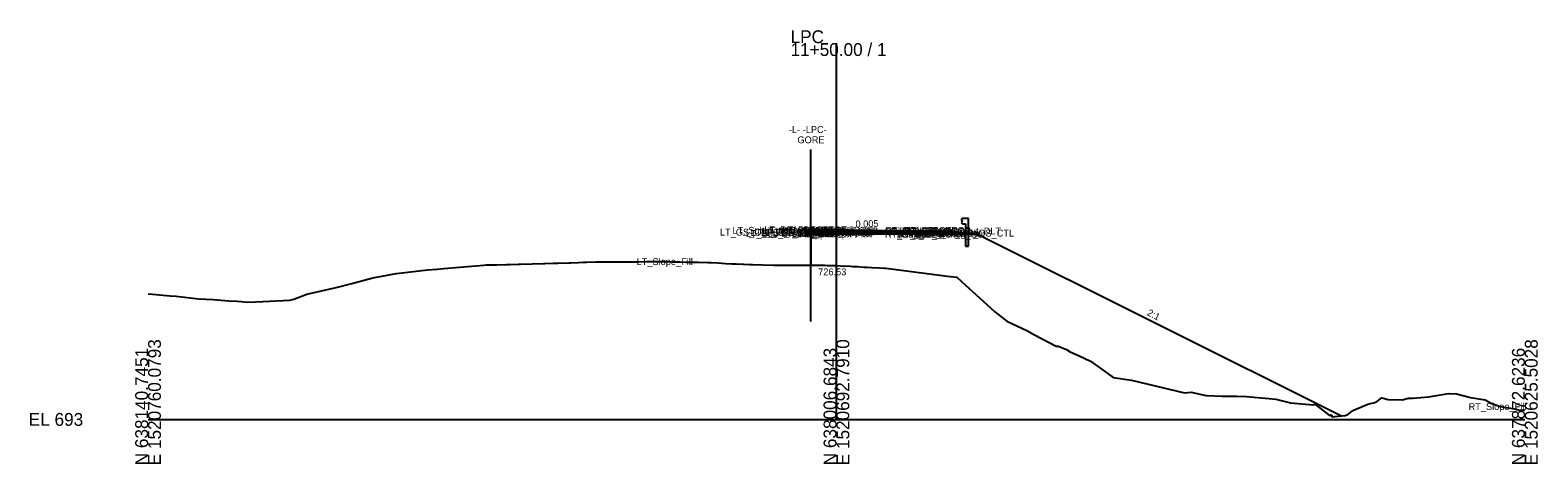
# Model space of a CAD drawing. Extents: x -26 to 303, y -10 to 4521.
# Drawn here: x -25.7 to 302.8, y 1490.3 to 1584.9 of the extents above; entities that cross this region are included whole.
import ezdxf

# ---------------------------------------------------------------- set-up
doc = ezdxf.new("R2010")
doc.units = 0
for name, color, linetype in [('Default', 7, 'Continuous'), ('Exist Cross Section Cell', 7, 'Continuous'), ('Exist XS Center Line Elevation Label', 7, 'Continuous'), ('Exist XS Ground Line', 7, 'Continuous'), ('Prop CMT Guardrail Graphics', 7, 'Continuous'), ('Prop CMT Pvmt Course 1', 7, 'Continuous'), ('Prop CMT Pvmt Course 2', 7, 'Continuous'), ('Prop CMT Pvmt Course 3', 7, 'Continuous'), ('Prop CMT Pvmt Surface', 7, 'Continuous'), ('Prop CMT Pvmt Surface Shoulder', 7, 'Continuous'), ('Prop CMT Shld Paved Course 1', 7, 'Continuous'), ('Prop CMT Shld Paved Course 2', 7, 'Continuous'), ('Prop CMT Shld Paved Course 3', 7, 'Continuous'), ('Prop CMT Slope Grass', 7, 'Continuous'), ('Prop CMT Subgrade Earthwork', 7, 'Continuous'), ('Prop XS Earthwork Shape', 7, 'Continuous'), ('Prop XS Shear Point Element', 7, 'Continuous'), ('Prop XS Shear Point Label', 7, 'Continuous')]:
    doc.layers.add(name, color=color, linetype=linetype)

msp = doc.modelspace()

# ---------------------------------------------------------------- linework, layer by layer
at = {"layer": 'Exist Cross Section Cell'}
for p, q in [((150, 1500), (150, 1582.04)), ((0, 1500), (150, 1500)), ((150, 1500), (300, 1500))]:
    msp.add_line(p, q, dxfattribs=at)
at = {"layer": 'Exist XS Ground Line'}
msp.add_lwpolyline([(0, 1527.35), (1, 1527.3), (4.04, 1527.04), (4.81, 1526.96), (6.12, 1526.87), (11.01, 1526.29), (14.21, 1526.11), (17.6, 1525.89), (19.35, 1525.77), (20.32, 1525.69), (21.74, 1525.54), (24.98, 1525.7), (30.89, 1525.98), (31.79, 1526.24), (34.61, 1527.3), (40.97, 1528.78), (44.43, 1529.67), (48.97, 1530.89), (54.08, 1531.82), (54.14, 1531.84), (60.91, 1532.64), (63.01, 1532.74), (64.44, 1532.91), (67.88, 1533.2), (73.15, 1533.64), (73.66, 1533.67), (74.34, 1533.69), (75.29, 1533.72), (75.33, 1533.71), (76, 1533.74), (78.08, 1533.78), (78.92, 1533.79), (80.63, 1533.84), (80.88, 1533.84), (81.13, 1533.85), (83.68, 1533.91), (86.17, 1533.98), (86.47, 1533.99), (88.24, 1534.04), (89.27, 1534.07), (91.76, 1534.15), (91.96, 1534.15), (92.07, 1534.16), (93.83, 1534.22), (94.87, 1534.25), (95.4, 1534.29), (95.6, 1534.3), (97.57, 1534.33), (97.6, 1534.33), (97.66, 1534.33), (99.42, 1534.35), (100.46, 1534.36), (101.27, 1534.36), (102.93, 1534.36), (103.14, 1534.36), (103.25, 1534.36), (105, 1534.37), (106.04, 1534.38), (106.86, 1534.39), (108.51, 1534.41), (108.72, 1534.41), (108.82, 1534.41), (110.58, 1534.41), (111.62, 1534.41), (112.86, 1534.4), (114.09, 1534.38), (114.3, 1534.38), (114.41, 1534.38), (114.57, 1534.38), (114.96, 1534.38), (115.88, 1534.36), (117.21, 1534.32), (118.01, 1534.3), (119.65, 1534.26), (120.01, 1534.25), (122.01, 1534.2), (122.7, 1534.19), (124.12, 1534.13), (124.21, 1534.13), (125.03, 1534.07), (125.81, 1534.01), (127.21, 1533.95), (128.17, 1533.91), (129.6, 1533.85), (129.83, 1533.84), (131.16, 1533.8), (131.45, 1533.79), (131.68, 1533.78), (134.07, 1533.7), (136.38, 1533.66), (136.83, 1533.64), (137.29, 1533.64), (139.63, 1533.63), (141.94, 1533.63), (142.42, 1533.64), (142.66, 1533.64), (144.13, 1533.64), (144.27, 1533.63), (145.2, 1533.62), (147.5, 1533.6), (147.99, 1533.59), (148.49, 1533.57), (150, 1533.54), (150.78, 1533.52), (153.04, 1533.39), (153.58, 1533.36), (153.72, 1533.35), (154.58, 1533.31), (155.99, 1533.22), (156.7, 1533.17), (157.71, 1533.11), (159.35, 1533.03), (160.44, 1532.98), (160.53, 1532.98), (160.74, 1532.95), (174.18, 1531.25), (176.23, 1530.98), (178.14, 1529.26), (181.18, 1526.54), (184.53, 1523.47), (187.16, 1521.41), (191.49, 1519.37), (193.14, 1518.43), (197.91, 1515.96), (198.3, 1515.96), (200.14, 1515.24), (200.94, 1514.72), (202.74, 1513.95), (205.35, 1512.73), (208.4, 1510.52), (210.3, 1509.13), (214.3, 1508.54), (225.85, 1505.77), (227.3, 1505.93), (230.5, 1505.18), (230.8, 1505.22), (234.06, 1505.08), (237.27, 1505.09), (239.37, 1505.02), (244.22, 1504.58), (245.78, 1504.44), (248.62, 1503.71), (248.97, 1503.61), (249, 1503.59), (253.88, 1503.21), (254.24, 1503.34), (254.27, 1503.38), (254.82, 1502.9), (257.45, 1500.88), (257.76, 1501), (257.85, 1500.94), (258.03, 1500.55), (258.57, 1500.64), (260.84, 1500.83), (261.01, 1500.92), (261.36, 1501.01), (262.42, 1501.87), (262.53, 1501.91), (265.8, 1503.3), (267.59, 1503.73), (268.85, 1504.7), (268.86, 1504.7), (270.2, 1504.33), (273.33, 1504.27), (274.56, 1504.6), (275.65, 1504.62), (278.99, 1504.89), (283.34, 1505.63), (285.08, 1505.56), (288.18, 1504.8), (291.33, 1504.25), (292.7, 1503.53), (294.63, 1502.79), (298.19, 1502.26), (298.67, 1502.05), (300, 1502.06)], dxfattribs=at)
at = {"layer": 'Prop CMT Guardrail Graphics'}
for points in [[(178.78, 1543.78), (177.45, 1543.78), (177.18, 1543.48)], [(177.18, 1543.48), (177.45, 1543.19)], [(177.45, 1543.19), (177.18, 1542.9)], [(177.18, 1542.9), (177.45, 1542.61), (178.12, 1542.61)], [(178.12, 1542.61), (178.12, 1537.78)], [(178.78, 1537.78), (178.78, 1543.78)], [(178.12, 1537.78), (178.78, 1537.78)]]:
    msp.add_lwpolyline(points, dxfattribs=at)
at = {"layer": 'Prop CMT Pvmt Course 1'}
msp.add_line((150, 1541.3), (167, 1541.22), dxfattribs=at)
for points in [[(150, 1541.3), (144.41, 1541.32)], [(144.41, 1541.32), (144.41, 1541.07)], [(144.41, 1541.07), (150, 1541.05)], [(150, 1541.05), (150, 1541.3)], [(150, 1541.05), (150, 1541.3)], [(167, 1540.97), (150, 1541.05)], [(167, 1541.22), (167, 1540.97)]]:
    msp.add_lwpolyline(points, dxfattribs=at)
msp.add_lwpolyline([(150, 1541.05), (150, 1541.17), (150, 1541.17), (150, 1541.05)], close=True, dxfattribs=at)
msp.add_lwpolyline([(150, 1541.05), (150, 1541.17), (150, 1541.17), (150, 1541.05)], close=True, dxfattribs=at)
at = {"layer": 'Prop CMT Pvmt Course 2'}
for points in [[(150, 1541.05), (144.41, 1541.07)], [(144.41, 1541.07), (144.41, 1540.74)], [(150, 1540.72), (150, 1541.05)], [(150, 1540.72), (150, 1541.05)], [(150, 1541.05), (167, 1540.97)], [(167, 1540.97), (167, 1540.64)], [(144.41, 1540.74), (150, 1540.72)], [(167, 1540.64), (150, 1540.72)]]:
    msp.add_lwpolyline(points, dxfattribs=at)
at = {"layer": 'Prop CMT Pvmt Course 3'}
for points in [[(150, 1540.72), (144.41, 1540.74)], [(144.41, 1540.74), (144.41, 1540.49)], [(144.41, 1540.49), (150, 1540.47)], [(150, 1540.47), (150, 1540.72)], [(150, 1540.72), (167, 1540.64)], [(150, 1540.47), (150, 1540.72)], [(167, 1540.39), (150, 1540.47)], [(167, 1540.64), (167, 1540.39)]]:
    msp.add_lwpolyline(points, dxfattribs=at)
at = {"layer": 'Prop CMT Pvmt Surface'}
for points in [[(150, 1541.3), (144.41, 1541.32)], [(150, 1541.3), (167, 1541.22)]]:
    msp.add_lwpolyline(points, dxfattribs=at)
at = {"layer": 'Prop CMT Pvmt Surface Shoulder'}
msp.add_lwpolyline([(167, 1541.22), (171, 1541.2)], dxfattribs=at)
at = {"layer": 'Prop CMT Shld Paved Course 1'}
for p in [(171.27, 1540.93), (177.18, 1540.8)]:
    msp.add_line(p, (177.18, 1540.55), dxfattribs=at)
for points in [[(144.41, 1541.07), (144.41, 1541.32)], [(167, 1541.22), (171, 1541.2), (171.25, 1540.95)], [(167, 1540.97), (167, 1541.22)], [(170.99, 1540.95), (167, 1540.97)]]:
    msp.add_lwpolyline(points, dxfattribs=at)
at = {"layer": 'Prop CMT Shld Paved Course 2'}
for points in [[(144.41, 1540.74), (144.41, 1541.07)], [(167, 1540.97), (171.25, 1540.95), (171.58, 1540.62)], [(167, 1540.64), (167, 1540.97)], [(171.58, 1540.62), (167, 1540.64)]]:
    msp.add_lwpolyline(points, dxfattribs=at)
at = {"layer": 'Prop CMT Shld Paved Course 3'}
msp.add_line((171.58, 1540.62), (171.83, 1540.37), dxfattribs=at)
for points in [[(144.41, 1540.49), (144.41, 1540.74)], [(167, 1540.39), (167, 1540.64)], [(167, 1540.64), (171.58, 1540.62), (171.83, 1540.37)], [(172.33, 1540.36), (167, 1540.39)]]:
    msp.add_lwpolyline(points, dxfattribs=at)
at = {"layer": 'Prop CMT Slope Grass'}
for p, q in [((144.41, 1541.32), (144.41, 1533.63)), ((171, 1541.2), (180.18, 1540.61)), ((259.9, 1500.75), (180.18, 1540.61))]:
    msp.add_line(p, q, dxfattribs=at)
at = {"layer": 'Prop CMT Subgrade Earthwork'}
for points in [[(150, 1540.47), (144.41, 1540.49)], [(150, 1540.47), (167, 1540.39)], [(167, 1540.39), (180.74, 1540.33)]]:
    msp.add_lwpolyline(points, dxfattribs=at)
at = {"layer": 'Prop XS Earthwork Shape'}
msp.add_lwpolyline([(144.41, 1540.49), (144.41, 1533.63), (145.2, 1533.62), (147.5, 1533.6), (147.99, 1533.59), (148.49, 1533.57), (150, 1533.54), (150.78, 1533.52), (153.04, 1533.39), (153.58, 1533.36), (153.72, 1533.35), (154.58, 1533.31), (155.99, 1533.22), (156.7, 1533.17), (157.71, 1533.11), (159.35, 1533.03), (160.44, 1532.98), (160.74, 1532.95), (174.18, 1531.25), (176.23, 1530.98), (178.14, 1529.26), (181.18, 1526.54), (184.53, 1523.47), (187.16, 1521.41), (191.49, 1519.37), (193.14, 1518.43), (197.91, 1515.96), (198.3, 1515.96), (200.14, 1515.24), (200.94, 1514.72), (202.74, 1513.95), (205.35, 1512.73), (208.4, 1510.52), (210.3, 1509.13), (214.3, 1508.54), (225.85, 1505.77), (227.3, 1505.93), (230.5, 1505.18), (230.8, 1505.22), (234.06, 1505.08), (237.27, 1505.09), (239.37, 1505.02), (244.22, 1504.58), (245.78, 1504.44), (248.62, 1503.71), (248.97, 1503.61), (253.88, 1503.21), (254.24, 1503.34), (254.82, 1502.9), (257.45, 1500.88), (257.76, 1501), (258.03, 1500.55), (258.57, 1500.64), (259.9, 1500.75), (180.74, 1540.33), (167, 1540.39), (150, 1540.47)], close=True, dxfattribs=at)
at = {"layer": 'Prop XS Shear Point Label'}
msp.add_line((144.4, 1521.38), (144.4, 1558.87), dxfattribs=at)

# ---------------------------------------------------------------- texts
at = {"layer": 'Default'}
msp.add_text('-', height=0.0001, dxfattribs=at).set_placement((0, 1500))
at = {"layer": 'Exist Cross Section Cell'}
for s, p in [('LPC', (140, 1582.04)), ('11+50.00 / 1', (140, 1579.24)), ('EL 693', (-26, 1498.6))]:
    msp.add_text(s, height=2.8, dxfattribs=at).set_placement(p)
for s, p in [('N 638140.7451', (0, 1490)), ('E 1520760.0793', (2.8, 1490)), ('N 638006.6843', (150, 1490)), ('E 1520692.7910', (152.8, 1490)), ('N 637872.6236', (300, 1490)), ('E 1520625.5028', (302.8, 1490))]:
    msp.add_text(s, height=2.8, rotation=90, dxfattribs=at).set_placement(p)
at = {"layer": 'Exist XS Center Line Elevation Label'}
for s, p in [('-L- -LPC- ', (139.64, 1562.46)), ('GORE', (141.5, 1560.21)), ('726.53', (146.02, 1531.42))]:
    msp.add_text(s, height=1.5, dxfattribs=at).set_placement(p)
for s, rotation, p in [('0.005', 1.2581, (154.17, 1541.86)), ('2:1', 332.3479, (217.54, 1522.8))]:
    msp.add_text(s, height=1.5, rotation=rotation, dxfattribs=at).set_placement(p)
at = {"layer": 'Prop XS Shear Point Element'}
for s, p in [('LT_GS_OS_CTL', (124.61, 1540.09)), ('LT_Sub_Trench_Out_DLT', (127.35, 1540.48)), ('LT_Sub_Trench_Out', (130.25, 1539.77)), ('LT_PS3_Shelf_Out', (131.32, 1540.01)), ('LT_PS3_OEOP', (133.52, 1540.01)), ('LT_PS2_OEOP', (133.85, 1540.34)), ('LT_PS1_OEOP', (134.27, 1540.59)), ('LT_PV2_OEOT', (138.03, 1540.32)), ('LT_PV3_OEOT', (138.03, 1539.99)), ('LT_Sub_OEOT', (138.07, 1539.74)), ('LT_PV1_OEOT', (138.21, 1540.57)), ('RT_PV2_OEEOP', (143, 1540.3)), ('RT_PV3_OEEOP', (143, 1539.97)), ('RT_Sub_OEEOP', (143.04, 1539.72)), ('LT_PV2_OEEOP', (143.09, 1540.3)), ('LT_PV3_OEEOP', (143.09, 1539.97)), ('LT_Sub_OEEOP', (143.12, 1539.72)), ('RT_PV1_OEEOP', (143.18, 1540.42)), ('LT_PV1_OEEOP', (143.27, 1540.42)), ('RT_PV2_IEEOP', (143.57, 1540.3)), ('LT_PV2_IEEOP', (143.66, 1540.3)), ('RT_PV1_IEEOP', (143.75, 1540.42)), ('LT_PV1_IEEOP', (143.84, 1540.42)), ('PV2_PGL', (146.02, 1540.3)), ('PV1_PGL', (146.2, 1540.55)), ('RT_PV2_OEOT', (160.53, 1540.22)), ('RT_PV3_OEOT', (160.53, 1539.89)), ('RT_Sub_OEOT', (160.56, 1539.64)), ('RT_PV1_OEOT', (160.71, 1540.47)), ('RT_Sub_Trench_Out_DLT', (161.92, 1540.32)), ('RT_Sub_Trench_Out', (163.41, 1539.61)), ('RT_PS3_Shelf_Out', (163.98, 1539.86)), ('RT_PS1_OEOP', (164.77, 1540.45)), ('RT_PS2_OEOP', (164.84, 1540.2)), ('RT_PS3_OEOP', (165.17, 1539.87)), ('RT_GS_OS_CTL', (173.11, 1539.87)), ('LT_Slope_Fill', (106.45, 1533.65)), ('RT_Slope_Fill', (287.75, 1502.04))]:
    msp.add_text(s, height=1.5, dxfattribs=at).set_placement(p)

doc.saveas('drawing.dxf')
